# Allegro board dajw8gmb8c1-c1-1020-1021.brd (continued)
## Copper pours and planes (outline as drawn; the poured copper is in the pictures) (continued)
+USB_SIDE0_PWR on BOTTOM (solid shape): 314.18,67.17 314.18,65.65 313.55,65.01 312.28,65.01 311.51,64.25 309.35,64.25 309,64.6 309,65.13 310.62,65.13 310.62,65.37 309.17,65.37 309.17,65.13 309,65.13 309,65.78 310.62,65.78 310.62,66.02 309.17,66.02 309.17,65.78 309,65.78 309,66.31 309.1,66.41 310.75,66.41 311.01,66.66 311.01,66.92 311.77,67.68 313.67,67.68
+USB_SIDE1_PWR on TOP (solid shape): 17.38,64.04 17.38,61.81 17.2,61.63 16.11,61.63 15.65,62.09 15.65,63.97 15.93,64.25 17.18,64.25
+USB_SIDE1_PWR on BOTTOM (solid shape): outline of 152 points within 13.29,60.03 21.32,65.09
+USB_SIDE1_PWR on IN2 (solid shape): outline of 84 points within 13.56,60.6 20.34,64.81
+USB_SIDE2_PWR on TOP (solid shape): 16.98,82.28 16.98,79.56 16.77,79.36 16.19,79.36 15.83,79.72 15.83,82.21 16.04,82.41 16.85,82.41
+USB_SIDE2_PWR on BOTTOM (solid shape): 24.6,57.87 24.6,56.86 24.56,56.82 23.63,56.82 23.62,56.83 23.35,56.83 23.2,56.68 22.77,56.68 22.31,57.14 22.31,57.34 23.02,58.05 23.02,58.51 23.26,58.75 23.72,58.75
+USB_SIDE2_PWR on BOTTOM (solid shape): 16.25,82.04 16.25,81.38 16.49,81.14 17.51,81.14 17.84,80.81 17.84,80.05 17.53,79.74 15.43,79.74 15.39,79.78 14.88,79.78 14.8,79.81 14.78,79.89 14.23,80.63 13.42,80.19 13.41,80.16 12.49,80.16 12.12,80.53 12.12,81.44 12.4,81.72 13.07,81.72 13.12,81.69 13.17,81.65 13.33,81.61 13.47,81.7 13.49,81.72 13.57,81.72 13.58,81.71 13.83,81.55 14.12,81.5 14.3,81.54 14.46,81.61 14.58,81.71 14.68,81.84 15.2,82.36 15.93,82.36
+USB_SIDE2_PWR on IN2 (solid shape): outline of 1108 points within 12.07,56.55 26.86,82.54
+USB_SIDE2_PWR on IN3 (solid shape): 17.18,81.95 17.18,79.46 16.9,79.18 14.92,79.18 14.62,79.48 14.79,79.91 14.67,80.35 14.1,80.66 13.51,80.38 12.48,80.38 12.39,80.47 12.39,81.64 12.42,81.71 12.48,81.74 12.52,81.75 12.57,81.76 12.88,81.79 13.16,81.66 13.32,81.61 13.46,81.68 13.53,81.7 13.6,81.68 14.31,81.53 14.78,82.08 14.78,82.1 14.99,82.31 16.82,82.31
+V_VDDQ on TOP (solid shape): 154.41,61.96 154.41,57.77 153.37,56.73 152.94,56.73 152.65,57.02 141.58,57.02 136,62.6 136,70.98 136.38,71.36 145.02,71.36
+V_VDDQ on TOP (solid shape): 228.13,72.02 228.13,69.15 227.36,68.39 225.61,68.39 225.2,68.79 224.6,68.79 224.19,68.39 222.31,68.39 222.03,68.67 222.03,71.16 222.89,72.02 226.2,72.02 226.3,72.12 228.02,72.12
+V_VDDQ on TOP (solid shape): outline of 149 points within 173.44,20.1 183.24,31.7
+V_VDDQ on TOP (solid shape): outline of 2130 points within 139.05,28.31 157.67,47.74
+V_VDDQ on BOTTOM (solid shape): outline of 196 points within 137.4,25.21 168.46,47.92
+V_VDDQ on SVCC (solid shape): outline of 375 points within 138.62,28.31 243.57,74.79
+V_VDDQ on IN2 (solid shape): outline of 2117 points within 139.51,37.91 159.34,62.11
+V_VDDQ_CPU on TOP (solid shape): outline of 3881 points within 127.97,69.07 144.55,88.4
+V_VDDQ_CPU on BOTTOM (solid shape): outline of 88 points within 125.28,69.29 137.01,79.26
+VCHGR on TOP (solid shape): 39.76,20.97 39.76,18.15 39.74,18.14 39.74,17.14 39.51,16.9 36.28,16.9 36.15,16.78 36.15,13.14 35.92,12.91 34.17,12.91 34.07,13.02 34.07,15.12 32.8,16.39 32.8,17.99 33.33,18.53 33.33,20.08 34.53,21.27 39.45,21.27
+VCHGR on BOTTOM (solid shape): 35.16,18.1 35.16,17.41 35.19,17.39 36.46,17.39 36.48,17.41 36.48,18.05 37.5,18.05 37.57,17.97 37.57,17 37.37,16.8 36.81,16.8 36.53,16.52 36.53,9.42 36.21,9.1 33.02,9.1 32.79,9.33 32.79,12.05 33.03,12.05 33.03,12 33.04,11.95 33.06,11.9 33.09,11.85 33.12,11.81 33.16,11.77 33.21,11.74 33.25,11.72 33.3,11.7 33.36,11.7 33.41,11.7 33.46,11.7 33.51,11.72 33.56,11.74 33.61,11.77 33.65,11.81 33.68,11.85 33.71,11.9 33.72,11.95 33.74,12 33.74,12.05 33.74,12.1 33.72,12.16 33.71,12.21 33.68,12.25 33.65,12.29 33.61,12.33 33.56,12.36 33.51,12.38 33.46,12.4 33.41,12.41 33.36,12.41 33.3,12.4 33.25,12.38 33.21,12.36 33.16,12.33 33.12,12.29 33.09,12.25 33.06,12.21 33.04,12.16 33.03,12.1 33.03,12.05 32.79,12.05 32.79,12.14 32.62,12.31 32.62,18.1 32.8,18.28 34.98,18.28
+VGACORE on TOP (solid shape): outline of 93 points within 188.55,61.71 213.43,78.95
+VGACORE on TOP (solid shape): outline of 203 points within 188.63,90.17 191.5,98.44
+VGACORE on TOP (solid shape): outline of 441 points within 193.61,90.18 198.1,98.69
+VGACORE on BOTTOM (solid shape): 195.77,79.2 195.83,79.2 196.96,78.07 197.32,78.07 197.75,77.63 197.75,71.66 197.44,71.36 196.71,71.36 196.38,71.03 196.38,69.68 196.3,69.61 196.3,69.23 196.43,69.1 219.36,69.1 219.85,68.62 219.85,60.79 219.38,60.32 210.54,60.32 209.34,61.52 201.68,61.52 201.28,61.92 197.77,61.92 197.76,61.91 195.71,61.91 195.49,61.99 195.27,61.91 194.98,61.91 194.95,61.94 191.52,61.94 191.14,62.32 191.14,73.27 191.42,73.54 192.34,73.54 192.75,73.96 193,74.21 192.97,74.56 192.97,74.95 193.15,75.13 193.15,78.59 193.76,79.2 193.76,79.34 193.96,79.54 195.42,79.54
+VGACORE on BOTTOM (solid shape): 197.55,92.58 197.66,92.6 197.72,92.51 197.72,91.57 197.73,91.47 197.77,91.38 197.77,91.28 197.69,91.23 197.26,91.23 196.26,90.23 196.24,90.23 195.84,89.84 195.84,89.32 195.82,89.23 195.82,89.15 195.79,89.07 195.72,89.04 194.25,89.04 194.16,89.1 194.18,89.21 194.73,89.76 194.73,89.9 195.01,90.18 195.15,90.18 195.71,90.74 195.88,90.74 196.21,91.07 196.22,91.08 196.32,91.15 196.4,91.25 196.4,91.26 196.73,91.59 196.73,91.76
+VGACORE on BOTTOM (solid shape): 197.62,94.57 197.7,94.54 197.72,94.46 197.72,94.42 197.72,93.94 197.73,93.86 197.77,93.78 197.73,93.73 197.7,93.67 197.07,93.04 197.07,93.04 196.07,92.04 196.07,91.86 195.93,91.73 195.92,91.72 195.82,91.65 195.75,91.55 195.74,91.54 195.6,91.4 195.43,91.4 194.9,90.87 194.88,90.87 194.68,90.81 194.55,90.66 194.55,90.65 194.07,90.17 194.07,90.04 193.5,89.47 193.48,89.46 193.32,89.31 193.28,89.08 193.26,89 193.18,88.96 192.44,88.96 192.36,88.87 192.35,88.85 192.32,88.84 192.24,88.81 192.2,88.88 192.19,88.91 192.19,89.08 192.14,89.14 192.14,89.24 192.47,89.57 192.54,89.57 192.73,89.76 192.73,89.98 193.03,90.28 193.25,90.28 195.04,92.07 195.04,92.07 195.15,92.15 195.22,92.25 195.22,92.26 195.73,92.76 195.73,92.81 196.02,93.1 196.04,93.1 196.22,93.16 196.34,93.31 196.37,93.39 196.38,93.46 196.48,93.57 196.54,93.57 197.54,94.57
+VGACORE on BOTTOM (solid shape): outline of 1266 points within 186.8,88.86 198.97,99.63
+VGACORE on SVCC (solid shape): 197.47,98.07 197.47,89.99 197,89.52 196.3,89.52 196.17,89.55 196.04,89.52 195.07,89.52 194.85,89.6 194.63,89.52 192.77,89.52 192.58,89.48 192.41,89.37 192.33,89.29 192.03,89.19 191.93,88.9 190.76,87.72 190.65,87.55 190.61,87.36 190.61,82.41 190.65,82.22 190.76,82.05 192.34,80.47 192.34,79.97 192.84,79.97 197.1,75.71 197.1,75.31 197.07,75.02 197.21,74.76 197.54,74.43 197.59,74.39 197.65,74.35 199.55,72.45 199.71,72.34 199.91,72.3 200.76,72.3 204.8,68.26 204.97,68.15 205.17,68.11 217,68.11 217,67.48 213.13,63.61 189.92,63.61 189.57,63.97 189.21,63.61 177.36,63.61 170.67,70.3 170.67,85.63 183.33,98.28 188.44,98.28 188.78,98.03 189.12,98.28 192.74,98.28 192.86,98.3 192.97,98.34 193.42,98.33 193.52,98.77 196.77,98.77
+VGACORE on IN2 (solid shape): outline of 4417 points within 180.48,73.93 197.05,99.83
+VGACORE on IN3 (solid shape): outline of 2517 points within 184.56,88.15 200.57,99.28
+VH28 on TOP (solid shape): 201.05,22.36 201.05,22.35 201.07,22.33 201.82,22.33 201.84,22.31 201.84,22.16 201.81,22.13 201.01,22.13 201,22.11 200.26,22.11 200.08,22.29 198.97,22.29 198.86,22.39 198.86,23.2 199.09,23.43 199.98,23.43
G5934VIN on TOP (solid shape): 201.81,21.09 201.81,20.59 200.39,19.16 200.39,19.14 200.21,18.96 199.27,18.96 199.12,19.11 199.12,20.69 199.23,20.8 200.96,20.8 201.1,20.94 201.1,21.07 201.15,21.12 201.78,21.12
L_SPK+ on TOP (solid shape): 308.52,40.27 308.52,39.71 307.7,38.9 307.7,37.65 307.68,37.63 307.48,37.63 307.42,37.68 307.42,40.27 307.5,40.35 308.44,40.35
L_SPK+ on BOTTOM (solid shape): 293.18,32.17 293.18,31.56 293,31.38 290.97,31.38 290.89,31.46 290.89,32.12 291.02,32.24 293.1,32.24
L_SPK+ on IN1 (solid shape): 292.57,32.63 292.57,31.86 292.06,31.36 291.17,31.36 291.02,31.51 291.02,32.52 291.37,32.88 292.31,32.88
L_SPK+ on IN1 (solid shape): outline of 236 points within 299.22,34.4 308.75,40.3
L_SPK+_R on BOTTOM (solid shape): 295.72,32.55 295.72,31.63 295.46,31.38 293.76,31.38 293.66,31.48 293.66,32.35 294.04,32.73 295.54,32.73
L_SPK+_R on BOTTOM (solid shape): 303.51,35.14 303.51,34.45 303.31,34.25 300.85,34.25 300.68,34.42 300.68,34.92 301.1,35.34 303.31,35.34
L_SPK+_R on IN2 (solid shape): outline of 199 points within 294.55,31.43 302.29,35.05
L_SPK- on TOP (solid shape): 307.25,40.3 307.25,39.03 307.18,38.96 307.18,37.68 307.16,37.65 306.95,37.65 306.9,37.71 306.9,38.98 306.84,39.04 306.84,40.3 306.97,40.42 307.12,40.42
L_SPK- on BOTTOM (solid shape): 293,33.87 293,33.11 292.96,33.07 291.4,33.07 291.16,33.3 291.16,34.68 291.47,34.99 291.88,34.99
L_SPK- on IN1 (solid shape): 292.34,35.72 292.34,33.9 292.03,33.59 291.78,33.59 291.22,34.15 291.22,35.5 291.63,35.9 292.16,35.9
L_SPK- on IN1 (solid shape): 307.22,40.3 307.22,37.93 306.79,37.5 304.22,37.5 304.05,37.68 304.05,38.42 304.43,38.8 306.46,38.8 306.79,39.13 306.79,40.22 306.94,40.37 307.15,40.37
L_SPK-_R on BOTTOM (solid shape): 303.34,36.54 303.69,36.54 304.02,36.21 304.02,35.72 303.84,35.55 301.56,35.55 300.87,36.23 300.87,36.33 301.23,36.69 303.18,36.69
L_SPK-_R on BOTTOM (solid shape): 295.8,34.16 295.8,33.9 295.61,33.71 295.61,33.21 295.54,33.13 293.68,33.13 293.63,33.18 293.63,34.25 293.66,34.28 295.69,34.28
L_SPK-_R on IN2 (solid shape): outline of 119 points within 294.56,33.77 302.67,38.09
LAN_MCTG on TOP (solid shape): 312.66,59.93 313.44,59.93 314.31,59.06 314.31,53.83 313.16,52.69 313.16,49.64 313.67,49.14 313.67,46.85 313.29,46.47 312.78,46.47 312.66,46.6 312.66,48.75 312.15,49.26 312.15,53.78 312.66,54.29 312.66,57.64 309.48,60.82 309.48,61.96 309.74,62.22 310.37,62.22
LAN_MCTG on BOTTOM (solid shape): 310.85,62.5 310.85,60.69 310.47,60.31 306.81,60.31 306.43,60.69 306.43,62.72 306.56,62.85 310.5,62.85
LAN_MCTG0 on TOP (solid shape): 312.38,57.34 312.38,55.71 312.23,55.56 311.13,55.56 310.93,55.76 310.93,57.21 311.29,57.57 312.15,57.57
LAN_MCTG1 on TOP (solid shape): 312.38,55.18 312.38,54.49 312.35,54.49 311.82,53.96 311.82,53.58 311.64,53.4 311.08,53.4 310.8,53.68 310.8,55.13 311.03,55.36 312.2,55.36
NV_PLLVDD on BOTTOM (solid shape): outline of 225 points within 184.92,89.62 187.23,91.63
PEX_PLLVDD on TOP (solid shape): 194.09,100.32 194.09,98.92 193.99,98.82 193.63,98.82 193.53,98.92 193.53,99.53 193.2,99.86 192.92,99.86 192.77,100.01 192.77,100.27 192.9,100.39 194.01,100.39
PEX_PLLVDD on TOP (solid shape): 195.6,112.27 195.6,108.33 193.4,106.13 192.72,106.13 192.59,106.26 192.59,106.64 193.1,107.15 193.1,108.88 193.51,109.28 193.51,112.25 193.66,112.41 195.46,112.41
PEX_PLLVDD on IN1 (solid shape): outline of 224 points within 191.88,99.91 194.7,106.68
R_SPK+ on TOP (solid shape): 305.88,40.42 305.88,39.38 305.68,39.19 305.68,37.68 305.66,37.65 305.46,37.65 305.41,37.71 305.41,39.08 305.34,39.14 305.34,40.35 305.47,40.47 305.82,40.47
R_SPK+ on BOTTOM (solid shape): 293.4,38.95 293.4,38.42 293.89,37.93 293.89,37.65 293.76,37.53 292.36,37.53 292.07,37.82 292.07,38.97 292.22,39.12 293.23,39.12
R_SPK+ on IN1 (solid shape): 294.72,38.64 294.72,38.04 294.19,37.5 293.1,37.5 292.72,37.88 292.72,38.29 293.15,38.72 294.65,38.72
R_SPK+ on IN1 (solid shape): 305.04,41.06 305.37,41.06 305.88,40.55 305.88,39.41 305.69,39.22 304.79,39.22 304.02,39.99 303.46,39.99 303.13,40.32 303.13,41.06 303.46,41.39 304.71,41.39
R_SPK+_R on BOTTOM (solid shape): 295.65,38.98 295.65,37.68 295.37,37.4 294.72,37.4 293.75,38.37 293.75,39.21 293.82,39.28 295.35,39.28
R_SPK- on TOP (solid shape): 306.59,40.4 306.59,39.39 306.19,39 306.19,37.68 306.17,37.65 305.96,37.65 305.91,37.71 305.91,39.19 306.03,39.31 306.03,40.42 306.08,40.47 306.51,40.47
R_SPK- on BOTTOM (solid shape): 293.25,36.84 293.25,35.83 292.97,35.55 291.98,35.55 291.97,35.56 291.36,35.56 291.24,35.67 291.24,36.16 291.8,36.71 291.8,37.08 291.96,37.24 292.86,37.24
R_SPK- on IN1 (solid shape): 292.97,37.07 292.97,36.71 292.72,36.46 291.42,36.46 291.14,36.74 291.14,37.53 291.5,37.88 292.16,37.88
R_SPK- on IN1 (solid shape): 306.81,41.64 306.81,40.58 306.56,40.32 306.56,39.36 306.43,39.23 306.18,39.23 306.05,39.36 306.05,40.83 305.24,41.64 305.24,42.07 305.42,42.25 306.21,42.25
R_SPK-_R on BOTTOM (solid shape): 295.66,36.23 295.66,35.77 295.72,35.72 295.72,35.14 295.44,34.86 293.81,34.86 293.58,35.09 293.58,36.28 293.72,36.42 295.47,36.42
REG_OUT on TOP (solid shape): 288.15,46.47 288.15,45.66 287.69,45.2 286.88,45.2 286.62,45.45 286.62,46.09 287.09,46.56 288.06,46.56
REG_OUT on BOTTOM (solid shape): 287.76,45.96 287.76,45.12 287.1,44.45 285.24,44.45 284.84,44.06 282.56,44.06 282.33,44.28 282.33,45.35 282.43,45.45 284.72,45.45 285.48,46.21 287.51,46.21
RT8240DH on BOTTOM (solid shape): 194.67,126.53 194.67,125.61 194.64,125.58 192.98,125.58 192.87,125.69 192.87,126.55 192.97,126.66 194.55,126.66
RT8240DH on IN1 (solid shape): 194.12,126.5 194.12,125.74 193.89,125.51 193.2,125.51 192.9,125.82 192.9,126.58 192.95,126.63 193.99,126.63
RT8240LX on BOTTOM (solid shape): 193.06,125.27 194.59,125.27 194.67,125.19 194.67,123 194.98,122.69 194.98,121.6 195.13,121.45 198.03,121.45 198.46,121.02 198.46,115.61 198.17,115.31 191.74,115.31 189.62,117.44 189.62,125.18 189.9,125.46 192.88,125.46
SP_PLLVDD on TOP (solid shape): 185.73,93.61 185.73,92.44 185.58,92.29 184.67,92.29 183.98,91.6 183.98,90.89 183.4,90.31 176.92,90.31 176.67,90.56 175.5,90.56 175.34,90.71 175.34,91.53 175.62,91.81 177.4,91.81 177.43,91.8 177.44,91.78 177.45,91.61 177.66,91.4 177.96,91.4 178.08,91.53 182.51,91.53 182.51,91.48 182.52,91.42 182.53,91.37 182.55,91.32 182.58,91.28 182.62,91.24 182.66,91.21 182.71,91.18 182.76,91.16 182.81,91.15 182.86,91.15 182.92,91.15 182.97,91.16 183.02,91.18 183.06,91.21 183.11,91.24 183.14,91.28 183.17,91.32 183.2,91.37 183.21,91.42 183.22,91.48 183.22,91.53 183.21,91.58 183.2,91.63 183.17,91.68 183.14,91.72 183.11,91.76 183.06,91.8 183.02,91.82 182.97,91.84 182.92,91.86 182.86,91.86 182.81,91.86 182.76,91.84 182.71,91.82 182.66,91.8 182.62,91.76 182.58,91.72 182.55,91.68 182.53,91.63 182.52,91.58 182.51,91.53 178.08,91.53 178.16,91.61 178.16,91.66 178.31,91.81 178.9,91.81 179.41,92.32 181.11,92.32 181.26,92.47 181.26,92.87 182.13,93.74 185.61,93.74
SP_PLLVDD on BOTTOM (solid shape): outline of 112 points within 185.27,92.06 187,93.74
SUB_GND on SGND (solid shape): 286.7,30.08 286.7,30.06 288.17,28.59 293.81,28.59 295.08,27.32 296.6,27.32 296.76,27.16 296.76,25.2 296.96,25 296.96,24.68 296.75,24.47 294.96,24.47 293.69,25.74 288.76,25.74 286.11,28.39 286.11,29.83 286.42,30.14 286.64,30.14
SUB_GND on IN1 (solid shape): 288.93,28.03 291.14,28.03 291.52,27.65 291.52,26.25 291.12,25.84 288.04,25.84 286.37,27.52 286.37,29.53 286.52,29.68 287.28,29.68
SUB_GND on SVCC (solid shape): 286.72,30.06 286.74,30.02 286.77,29.98 288.09,28.66 288.18,28.6 288.28,28.59 293.81,28.59 295,27.39 295.09,27.33 295.19,27.32 296.6,27.32 296.76,27.16 296.76,25.32 296.77,25.22 296.83,25.13 296.96,25 296.96,24.68 296.75,24.47 294.96,24.47 293.76,25.67 293.68,25.72 293.58,25.74 288.76,25.74 286.11,28.39 286.11,29.83 286.42,30.14 286.64,30.14
SUB_GND on SGND1 (solid shape): 286.7,30.08 286.7,30.06 288.17,28.59 293.81,28.59 295.08,27.32 296.6,27.32 296.76,27.16 296.76,25.2 296.96,25 296.96,24.68 296.75,24.47 294.96,24.47 293.69,25.74 288.76,25.74 286.11,28.39 286.11,29.83 286.42,30.14 286.64,30.14
SUB_OUT+ on BOTTOM (solid shape): 295.61,28.54 295.61,27.95 295.21,27.55 293.76,27.55 293.68,27.62 293.68,28.41 294.06,28.79 295.36,28.79
SUB_OUT+_L on TOP (solid shape): 289.67,31.81 289.67,30.69 289.67,30.65 289.67,30.01 289.67,29.96 289.67,29.68 289.77,29.58 290.03,29.58 290.33,29.27 290.33,27.85 290.19,27.71 288.96,27.71 288.76,27.91 288.76,29.09 288.48,29.37 288.48,30.68 288.31,30.85 288.31,31.85 288.43,31.96 289.52,31.96
SUB_OUT+_MOS on TOP (solid shape): 291.83,33.06 292.49,33.06 292.77,32.78 292.77,32.63 292.13,31.99 290.48,31.99 289.97,32.5 288.63,32.5 288.55,32.57 288.55,33.08 288.65,33.18 291.7,33.18
SUB_OUT+_MOS on BOTTOM (solid shape): 293.23,29.17 293.23,27.82 293.05,27.65 292.39,27.65 291.85,28.18 291.85,29.17 291.98,29.3 293.1,29.3
SUB_OUT+_MOS on IN1 (solid shape): 289.99,33.09 289.99,31.98 289.21,31.2 289.21,30.14 289.82,29.53 292.92,29.53 293.12,29.32 293.12,28.94 292.95,28.76 292.44,28.76 292.08,28.41 289.47,28.41 288.07,29.81 288.07,31.61 288.49,32.03 288.49,32.74 289.01,33.26 289.82,33.26
SUB_OUT- on BOTTOM (solid shape): 295.72,30.62 295.72,30.06 295.33,29.68 293.68,29.68 293.58,29.78 293.58,30.49 293.99,30.9 295.44,30.9
SUB_OUT-_L on TOP (solid shape): 287.76,27.04 287.76,26.2 287.87,26.1 290.28,26.1 290.41,25.97 290.41,24.67 290.08,24.34 289.39,24.34 289.19,24.55 289.19,24.95 289.01,25.13 286.95,25.13 286.66,25.42 286.66,26.95 286.88,27.16 287.64,27.16
SUB_OUT-_MOS on TOP (solid shape): 288.96,24.83 288.96,23.68 288.68,23.4 287.23,23.4 286.9,23.74 286.9,24.73 287.18,25.01 288.78,25.01
SUB_OUT-_MOS on BOTTOM (solid shape): 293.23,31.1 293.23,29.96 293.07,29.81 291.85,29.81 291.73,29.93 291.73,30.97 291.93,31.18 293.15,31.18
SUB_OUT-_MOS on IN1 (solid shape): 294.52,30.54 294.52,29.73 294.39,29.6 293.33,29.6 293.05,29.88 292.11,29.88 291.93,30.06 291.93,30.77 292.35,31.19 293.87,31.19
SUB_OUT-_MOS on IN1 (solid shape): 290.79,25.49 290.79,24.6 290.64,24.45 288.2,24.45 287.64,23.89 287,23.89 286.9,23.99 286.9,24.8 287.74,25.64 290.64,25.64
TRA_V_DAC on TOP (solid shape): 301.61,56.12 301.61,47.23 301.1,46.72 299.96,46.72 299.32,47.36 299.32,55.99 299.7,56.37 301.35,56.37
TRA_V_DAC on BOTTOM (solid shape): 301.48,48.63 301.48,48.03 300.47,48.03 300.47,47.51 301.48,47.51 301.48,46.98 301.35,46.85 299.19,46.85 298.94,47.1 298.94,47.99 299.7,48.75 301.35,48.75
TRA_V_DAC on BOTTOM (solid shape): 301.61,56.12 301.61,55.67 300.48,55.67 300.48,55.14 301.61,55.14 301.61,54.47 301.48,54.34 298.94,54.34 298.56,54.72 298.56,55.99 298.94,56.37 301.35,56.37
VCHGR_DH on BOTTOM (solid shape): 38.74,30.75 38.74,29.98 38.64,29.88 37.88,29.88 37.73,30.03 37.73,31.18 37.85,31.3 38.18,31.3
VCHGR_DH on IN3 (solid shape): 38.97,31.1 38.97,30.09 38.84,29.96 37.83,29.96 37.7,30.09 37.7,31.36 37.83,31.48 38.59,31.48
VCHGR_DL on BOTTOM (solid shape): 37.55,34.05 37.55,33.06 37.32,32.83 36.64,32.83 36.51,32.96 36.51,34.15 36.58,34.23 37.37,34.23
VCHGR_DL on IN3 (solid shape): 38.29,33.82 38.29,33.08 38.06,32.85 37.09,32.85 36.94,33.01 36.94,34.15 37.07,34.28 37.83,34.28
VCHGR_LX on BOTTOM (solid shape): 37.96,32.17 37.96,31.69 37.97,31.68 37.55,31.25 37.55,29.88 37.78,29.65 38.92,29.65 39.12,29.86 39.12,30.75 39.15,30.77 40.72,30.77 40.75,30.75 40.75,29.81 39.91,28.97 39.91,25.59 39.71,25.39 34.68,25.39 34.26,25.81 34.26,28.25 34.27,28.28 34.29,28.33 34.3,28.39 34.3,28.45 34.29,28.51 34.27,28.56 34.26,28.59 34.26,29.2 34.57,29.2 34.57,29.14 34.58,29.09 34.6,29.04 34.63,29 34.66,28.95 34.7,28.92 34.75,28.89 34.8,28.86 34.85,28.85 34.9,28.84 34.95,28.84 35.01,28.85 35.06,28.86 35.1,28.89 35.15,28.92 35.19,28.95 35.22,29 35.25,29.04 35.27,29.09 35.28,29.14 35.28,29.2 35.28,29.25 35.27,29.3 35.25,29.35 35.22,29.4 35.19,29.44 35.15,29.48 35.1,29.51 35.06,29.53 35.01,29.54 34.95,29.55 34.9,29.55 34.85,29.54 34.8,29.53 34.75,29.51 34.7,29.48 34.66,29.44 34.63,29.4 34.6,29.35 34.58,29.3 34.57,29.25 34.57,29.2 34.26,29.2 34.26,32.03 34.53,32.29 37.84,32.29
VCORE_AGND on IN1 (solid shape): outline of 839 points within 106.92,110.17 117.2,120.86
N126037216 on IN2 (solid shape): 160.76,91.53 160.76,90.79 160.61,90.64 159.93,90.64 159.65,90.92 159.65,91.53 159.8,91.68 160.61,91.68
N131687489 on TOP (solid shape): 283.45,41.9 283.45,41.24 283.61,41.07 284.04,41.07 284.54,40.58 284.54,40.04 284.39,39.89 283.02,39.89 282.89,40.02 282.89,40.78 282.41,41.26 282.41,41.69 282.68,41.97 283.37,41.97
N132058456 on TOP (solid shape): 129.86,28.43 129.86,28.24 129.81,28.2 127.53,28.2 126.27,26.94 125.08,26.94 124.93,27.1 124.93,27.61 125.13,27.81 126.43,27.81 127.09,28.48 129.81,28.48
N132067797 on BOTTOM (solid shape): 164.12,122.44 164.13,122.44 164.15,122.41 165.41,122.41 165.54,122.28 165.54,120.94 165.44,120.84 165.44,119.9 165.29,119.75 162.01,119.75 161.88,119.87 161.88,122.92 162.03,123.07 163.48,123.07
N132072905 on TOP (solid shape): 180.96,116.93 180.96,116.42 180.88,116.34 179.48,116.34 178.27,115.12 176.84,115.12 176.79,115.18 176.79,115.89 176.92,116.01 177.27,116.01 178.16,116.9 178.8,116.9 178.98,117.08 180.81,117.08
N132078232 on TOP (solid shape): 214.97,118.96 214.97,117.79 214.77,117.59 211.87,117.59 211.69,117.77 211.69,118.88 211.9,119.09 214.84,119.09
N132292966 on BOTTOM (solid shape): 129.01,122.91 129.01,121.12 128.99,121.09 126.77,121.09 126.77,120.59 128.99,120.59 129.07,120.51 129.07,118.91 128.94,118.78 124.16,118.78 123.96,118.99 123.96,123.02 124.02,123.09 128.84,123.09
N132293024 on BOTTOM (solid shape): 145.58,122.82 145.58,119.09 145.52,119.04 140.62,119.04 140.19,119.47 140.19,120.53 140.25,120.59 142.95,120.59 142.95,121.09 140.89,121.09 140.89,121.09 140.28,121.09 140.19,121.17 140.19,122.52 140.67,123 145.4,123
N132314788 on TOP (solid shape): 22.69,92.44 22.69,90.09 22.58,89.99 21.12,89.99 20.98,90.13 20.98,92.4 21.08,92.5 22.63,92.5
N132314946 on BOTTOM (solid shape): 33.41,59.02 35.81,59.02 36.87,57.95 36.87,56.34 36.81,56.27 35.89,56.27 35.85,56.31 35.85,57.04 35.81,57.08 34.54,57.08 34.5,57.05 34.5,56.29 34.43,56.21 31.67,56.21 31.46,56 31.12,56 30.88,56.25 30.88,57.07 30.91,57.13 30.92,57.19 30.92,57.49 30.92,57.51 30.92,58.03 30.46,58.48 30.46,59.17 30.59,59.3 33.13,59.3
N132315143 on BOTTOM (solid shape): 41.79,22.59 41.79,19.09 41.21,18.5 39.81,18.5 39.43,18.88 36.47,18.88 36.47,19.44 35.17,19.44 35.17,18.83 34.25,18.83 34.17,18.91 34.17,21.45 35.97,23.25 41.13,23.25
N133159595 on TOP (solid shape): 32.49,17.69 32.49,16.42 33.26,15.66 33.26,14.67 33.08,14.49 30.79,14.49 30.34,14.95 30.34,15.61 30.54,15.81 30.54,17.69 30.72,17.87 32.32,17.87
N133195216 on TOP (solid shape): 104.73,49.14 104.73,48.3 104.34,47.9 104.34,46.1 104.25,46.01 103.44,46.01 103.33,46.12 104.06,46.12 104.06,47.39 103.69,47.39 103.69,46.12 103.33,46.12 103.28,46.16 103.28,47.76 103.11,47.94 103.11,48.25 104.1,49.24 104.63,49.24

Small or netless copper shapes (teardrops, artwork), in the pictures only: 203 on TOP, 1039 on BOTTOM, 21 on IN1, 57 on IN2, 10 on IN3

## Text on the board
Ref Des/Silkscreen Bottom: B | RTC | FAN1 | DDR | TP | KB | FAN2 | HDD | BAT | WLAN | FP | LCD | SPK | MODEL:JW8G | SODIM ONLY SUPPORT DDR3L | DAJW8GMB8C1 | REV:C1
User.Comments: PARTITION_5 | PARTITION_2 | PARTITION_4 | PARTITION_3 | 142.0x150.0 | 329.50 | 128.70
Ref Des/Silkscreen Top: B | C | A | D | DAJW8GMB8C1 REV:C1
User.8: 18.00
User.12: +5V_ALW | +3.3V_RUN | GND | +VCCIN | +V_VDDQ | +1.05V_RUN | +VGACORE | +5V_RUN | +1.35V_GFX | +3.3V_ALW | SUB_GND | AGND
User.21: 328.80
User.23: 329.50 | 128.70
User.45: FIGURE | TYPE | Circle | Oblong | SIZE | 10.0 | 12.0 | 14.0 | 22.0 | 28.0 | 30.0 | 31.0 | 35.0 | 37.0 | 57.0 | 91.0 | 98.0 | 118.0 | 130.0 | 138.0 | 141.0 | 142.0 | 148.0 | 150.0 | 33.0 | 39.0 | 43.0 | 47.0 | 59.0 | 63.0 | 67.0 | 59.0x24.0 | 63.0x24.0 | 67.0x24.0 | 68.0x30.0 | 69.0x35.0 | 71.0x31.0 | 75.0x24.0 | 81.0x35.0 | 102.0x31.0 | DRILL CHART: TOP to BOTTOM | ALL UNITS ARE IN MILS | PLATED | NON-PLATED | ROTATION | - | 0.000 | 90.000 | QTY | 3676 | 31 | 701 | 19 | 22 | 1 | 27 | 8 | 2 | 4 | 3 | 4525 | 7 | 35 | TOTAL HOLES:
